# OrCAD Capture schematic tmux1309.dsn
size A
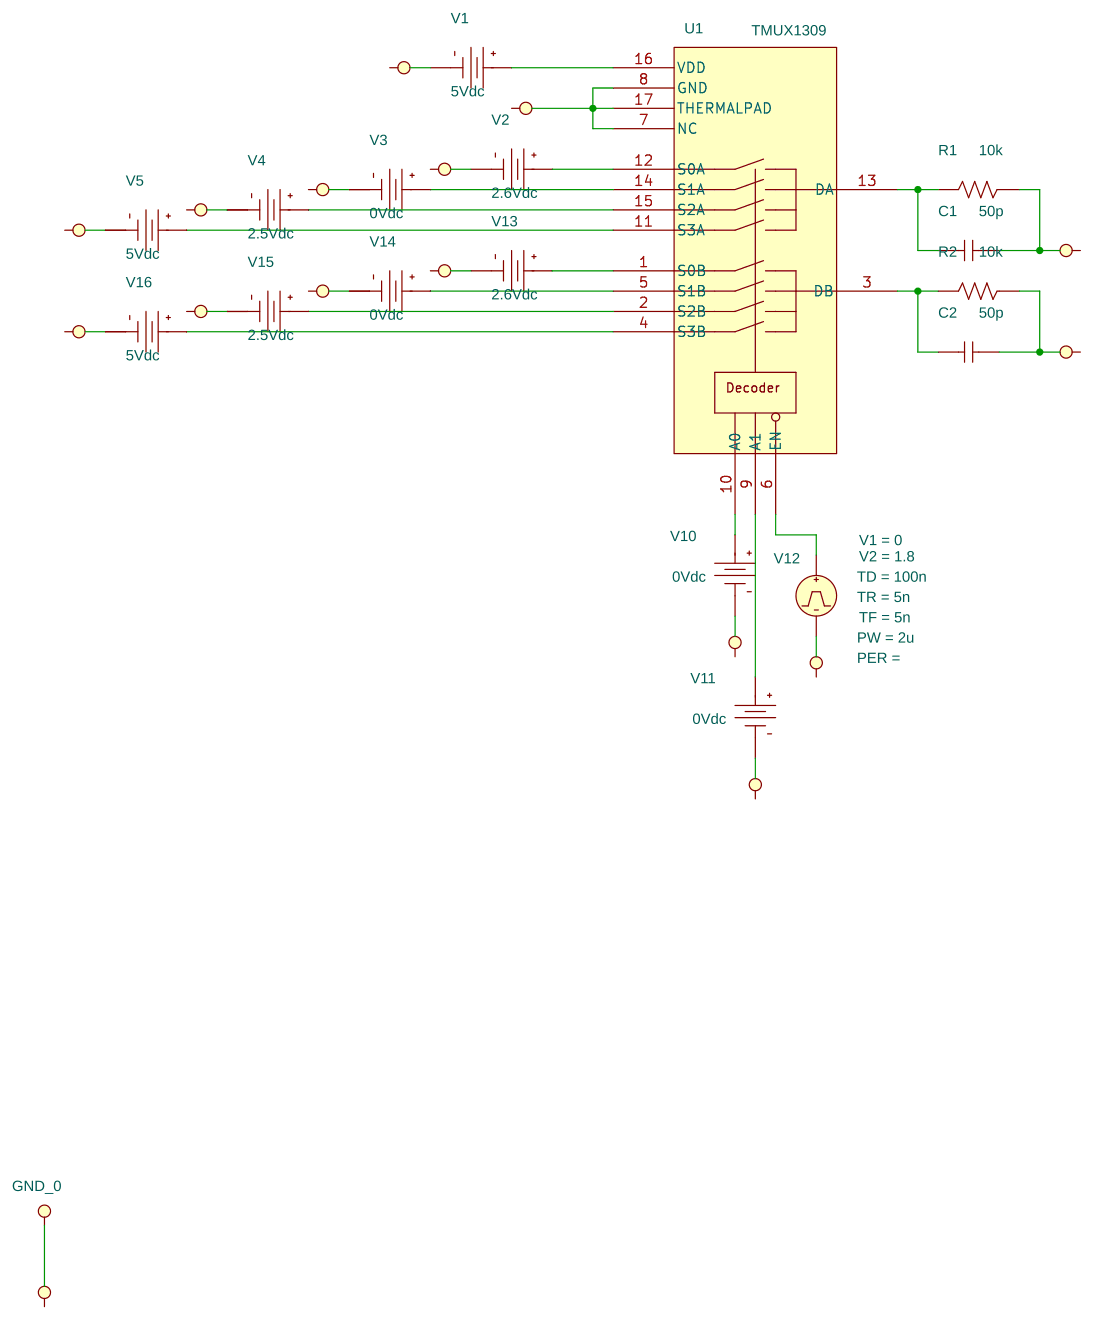
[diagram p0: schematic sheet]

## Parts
C1  50p  [cap196]
C2  50p  [cap196]
R1  10k  [AXRC05]
R2  10k  [AXRC05]
U1  TMUX1309
V1  VDC
V2  VDC
V3  VDC
V4  VDC
V5  VDC
V10  VDC
V11  VDC
V12  VPULSE
V13  VDC
V14  VDC
V15  VDC
V16  VDC

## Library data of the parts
C1 C2 = C
R1 R2 = R
U1 = TMUX1309
V1 V5 V16 = VDC: DC: 5Vdc
V2 V13 = VDC: DC: 2.6Vdc
V3 V10 V11 V14 = VDC: DC: 0Vdc
V4 V15 = VDC: DC: 2.5Vdc
V12 = VPULSE: PW: 2u; TD: 100n; TF: 5n; TR: 5n; V1: 0; V2: 1.8

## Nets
0: C1.2 C2.2 R1.1 R2.1 U1.7(NC) U1.8(GND) U1.17(THERMALPAD) V1.1(-) V2.1(-) V3.1(-) V4.1(-) V5.1(-) V10.1(-) V11.1(-) V12.2(-) V13.1(-) V14.1(-) V15.1(-) V16.1(-)
N14633: U1.16(VDD) V1.0(+)
N14725: U1.12(S0A) V2.0(+)
N14729: U1.14(S1A) V3.0(+)
N15051: U1.15(S2A) V4.0(+)
N15246: U1.11(S3A) V5.0(+)
N15722: C1.1 R1.2 U1.13(DA)
N15989: C2.1 R2.2 U1.3(DB)
N16404: U1.10(A0) V10.0(+)
N16408: U1.9(A1) V11.0(+)
N16475: U1.6(EN) V12.1(+)
N17469: U1.1(S0B) V13.0(+)
N17509: U1.5(S1B) V14.0(+)
N17549: U1.2(S2B) V15.0(+)
N17561: U1.4(S3B) V16.0(+)
